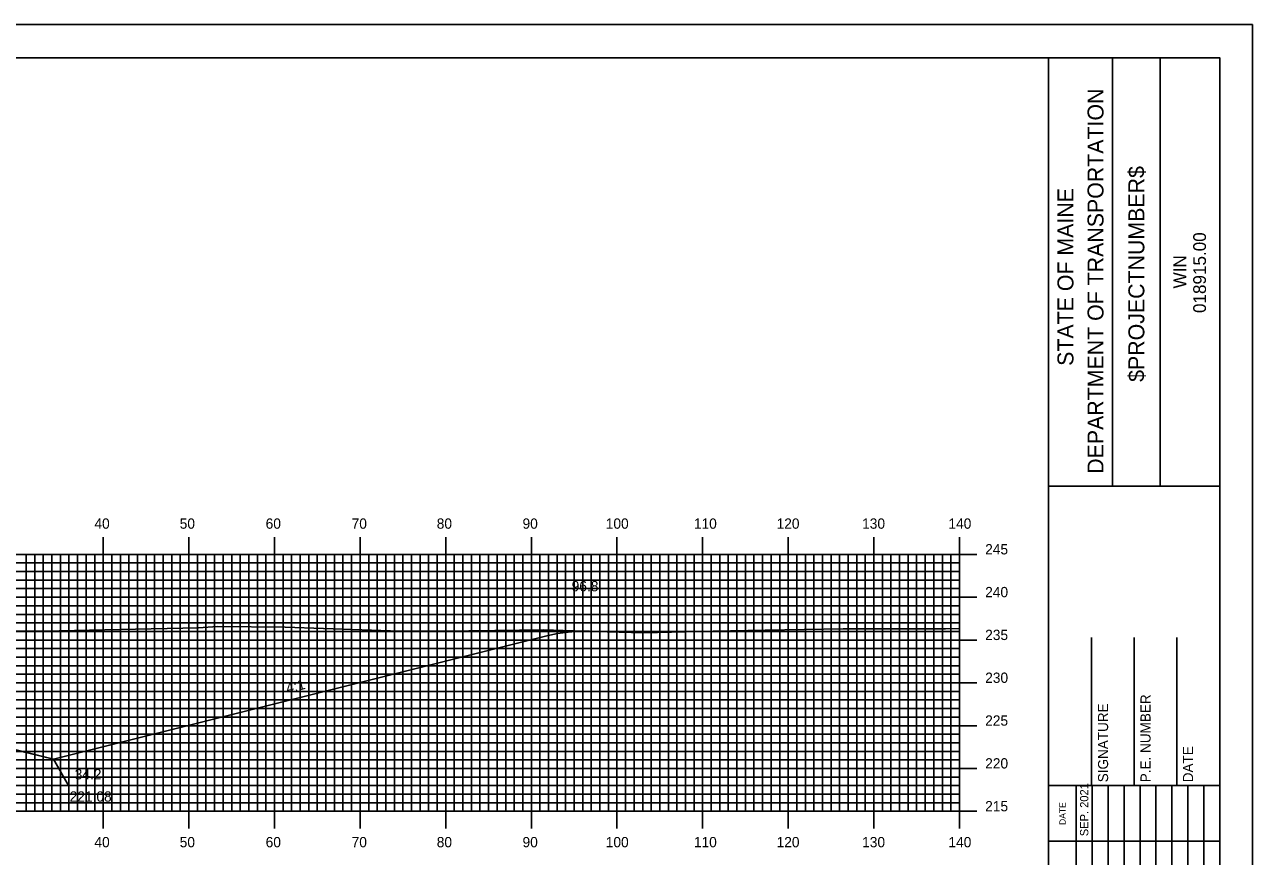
# Model space of a CAD drawing. Extents: x 1802323 to 1802666, y 442591 to 442811.
# Drawn here: x 1802519.4 to 1802662.8, y 442713.4 to 442810.5 of the extents above; entities that cross this region are included whole.
import ezdxf

# ---------------------------------------------------------------- set-up
doc = ezdxf.new("R2010")
doc.units = 0
for name, color, linetype in [('ANNOTATION', 7, 'Continuous'), ('BORDER', 7, 'Continuous'), ('D_Roadway_Centerline', 7, 'Continuous'), ('D_Roadway_SlopeLines', 7, 'Continuous'), ('D_Text_Standard', 7, 'Continuous'), ('H_V ANNOTATION', 7, 'Continuous'), ('MAJOR', 7, 'Continuous'), ('MINOR', 7, 'Continuous'), ('PLOT BOUNDARY', 7, 'Continuous'), ('S_Roadway_Centerline', 7, 'Continuous')]:
    doc.layers.add(name, color=color, linetype=linetype)

msp = doc.modelspace()

# ---------------------------------------------------------------- linework, layer by layer
at = {"layer": 'ANNOTATION'}
msp.add_lwpolyline([(1802530.23, 442721.67), (1802524.53, 442721.67), (1802522.78, 442724.74)], dxfattribs=at)
at = {"layer": 'BORDER'}
for p, q in [((1802639, 442596.67), (1802639, 442806.67)), ((1802646.46, 442756.66), (1802646.46, 442806.66)), ((1802652.05, 442756.66), (1802652.05, 442806.66)), ((1802639, 442756.65), (1802659, 442756.65)), ((1802644, 442721.67), (1802644, 442738.97)), ((1802649, 442721.67), (1802649, 442738.97)), ((1802654, 442721.67), (1802654, 442738.97)), ((1802639, 442721.67), (1802659, 442721.67))]:
    msp.add_line(p, q, dxfattribs=at)
msp.add_lwpolyline([(1802339, 442596.67), (1802659, 442596.67), (1802659, 442806.67), (1802339, 442806.67)], close=True, dxfattribs=at)
for points in [[(1802642.23, 442715.17), (1802642.23, 442721.67)], [(1802644.1, 442686.68), (1802644.1, 442721.67)], [(1802645.96, 442721.67), (1802645.96, 442686.68)], [(1802647.82, 442686.68), (1802647.82, 442721.67)], [(1802649.69, 442686.68), (1802649.69, 442721.67)], [(1802651.55, 442686.68), (1802651.55, 442721.67)], [(1802653.41, 442686.68), (1802653.41, 442721.67)], [(1802655.28, 442686.68), (1802655.28, 442721.67)], [(1802657.14, 442686.68), (1802657.14, 442721.67)], [(1802642.23, 442686.68), (1802642.23, 442720.26)], [(1802639, 442715.17), (1802659, 442715.17)]]:
    msp.add_lwpolyline(points, dxfattribs=at)
at = {"layer": 'D_Roadway_Centerline'}
msp.add_lwpolyline([(1802392.96, 442739.5), (1802394.21, 442739.46), (1802395.46, 442739.33), (1802396.71, 442739.13), (1802397.96, 442738.86), (1802454.43, 442724.74), (1802458.43, 442725.74), (1802468.6, 442728.29), (1802476.6, 442728.61), (1802488.6, 442728.85), (1802500.6, 442728.61), (1802508.6, 442728.29), (1802518.78, 442725.74), (1802522.78, 442724.74), (1802580.4, 442739.15), (1802581.65, 442739.42), (1802582.9, 442739.6), (1802584.15, 442739.69), (1802585.4, 442739.69)], dxfattribs=at)
at = {"layer": 'D_Roadway_SlopeLines'}
for points in [[(1802522.78, 442724.74), (1802580.4, 442739.15), (1802581.65, 442739.42), (1802582.9, 442739.6), (1802584.15, 442739.69), (1802585.4, 442739.69)], [(1802508.6, 442728.29), (1802522.78, 442724.74)]]:
    msp.add_lwpolyline(points, dxfattribs=at)
at = {"layer": 'MAJOR'}
for p, q in [((1802528.6, 442750.67), (1802528.6, 442748.67)), ((1802538.6, 442750.67), (1802538.6, 442748.67)), ((1802548.6, 442750.67), (1802548.6, 442748.67)), ((1802558.6, 442750.67), (1802558.6, 442748.67)), ((1802568.6, 442750.67), (1802568.6, 442748.67)), ((1802578.6, 442750.67), (1802578.6, 442748.67)), ((1802588.6, 442750.67), (1802588.6, 442748.67)), ((1802598.6, 442750.67), (1802598.6, 442748.67)), ((1802608.6, 442750.67), (1802608.6, 442748.67)), ((1802618.6, 442750.67), (1802618.6, 442748.67)), ((1802628.6, 442750.67), (1802628.6, 442748.67)), ((1802348.6, 442748.67), (1802628.6, 442748.67)), ((1802348.6, 442748.67), (1802628.6, 442748.67)), ((1802528.6, 442718.67), (1802528.6, 442748.67)), ((1802538.6, 442718.67), (1802538.6, 442748.67)), ((1802548.6, 442718.67), (1802548.6, 442748.67)), ((1802558.6, 442718.67), (1802558.6, 442748.67)), ((1802568.6, 442718.67), (1802568.6, 442748.67)), ((1802578.6, 442718.67), (1802578.6, 442748.67)), ((1802588.6, 442718.67), (1802588.6, 442748.67)), ((1802598.6, 442718.67), (1802598.6, 442748.67)), ((1802608.6, 442718.67), (1802608.6, 442748.67)), ((1802618.6, 442718.67), (1802618.6, 442748.67)), ((1802630.61, 442748.67), (1802626.6, 442748.67)), ((1802628.6, 442718.67), (1802628.6, 442748.67)), ((1802628.6, 442718.67), (1802628.6, 442748.67)), ((1802348.6, 442743.67), (1802628.6, 442743.67)), ((1802630.61, 442743.67), (1802626.6, 442743.67)), ((1802348.6, 442738.67), (1802628.6, 442738.67)), ((1802630.61, 442738.67), (1802626.6, 442738.67)), ((1802348.6, 442733.67), (1802628.6, 442733.67)), ((1802630.61, 442733.67), (1802626.6, 442733.67)), ((1802348.6, 442728.67), (1802628.6, 442728.67)), ((1802630.61, 442728.67), (1802626.6, 442728.67)), ((1802348.6, 442723.67), (1802628.6, 442723.67)), ((1802630.61, 442723.67), (1802626.6, 442723.67)), ((1802348.6, 442718.67), (1802628.6, 442718.67)), ((1802348.6, 442718.67), (1802628.6, 442718.67)), ((1802528.6, 442716.66), (1802528.6, 442718.67)), ((1802538.6, 442716.66), (1802538.6, 442718.67)), ((1802548.6, 442716.66), (1802548.6, 442718.67)), ((1802558.6, 442716.66), (1802558.6, 442718.67)), ((1802568.6, 442716.66), (1802568.6, 442718.67)), ((1802578.6, 442716.66), (1802578.6, 442718.67)), ((1802588.6, 442716.66), (1802588.6, 442718.67)), ((1802598.6, 442716.66), (1802598.6, 442718.67)), ((1802608.6, 442716.66), (1802608.6, 442718.67)), ((1802618.6, 442716.66), (1802618.6, 442718.67)), ((1802630.61, 442718.67), (1802626.6, 442718.67)), ((1802628.6, 442716.66), (1802628.6, 442718.67))]:
    msp.add_line(p, q, dxfattribs=at)
at = {"layer": 'MINOR'}
for p, q in [((1802519.6, 442718.67), (1802519.6, 442748.67)), ((1802520.6, 442718.67), (1802520.6, 442748.67)), ((1802521.6, 442718.67), (1802521.6, 442748.67)), ((1802522.6, 442718.67), (1802522.6, 442748.67)), ((1802523.6, 442718.67), (1802523.6, 442748.67)), ((1802524.6, 442718.67), (1802524.6, 442748.67)), ((1802525.6, 442718.67), (1802525.6, 442748.67)), ((1802526.6, 442718.67), (1802526.6, 442748.67)), ((1802527.6, 442718.67), (1802527.6, 442748.67)), ((1802529.6, 442718.67), (1802529.6, 442748.67)), ((1802530.6, 442718.67), (1802530.6, 442748.67)), ((1802531.6, 442718.67), (1802531.6, 442748.67)), ((1802532.6, 442718.67), (1802532.6, 442748.67)), ((1802533.6, 442718.67), (1802533.6, 442748.67)), ((1802534.6, 442718.67), (1802534.6, 442748.67)), ((1802535.6, 442718.67), (1802535.6, 442748.67)), ((1802536.6, 442718.67), (1802536.6, 442748.67)), ((1802537.6, 442718.67), (1802537.6, 442748.67)), ((1802539.6, 442718.67), (1802539.6, 442748.67)), ((1802540.6, 442718.67), (1802540.6, 442748.67)), ((1802541.6, 442718.67), (1802541.6, 442748.67)), ((1802542.6, 442718.67), (1802542.6, 442748.67)), ((1802543.6, 442718.67), (1802543.6, 442748.67)), ((1802544.6, 442718.67), (1802544.6, 442748.67)), ((1802545.6, 442718.67), (1802545.6, 442748.67)), ((1802546.6, 442718.67), (1802546.6, 442748.67)), ((1802547.6, 442718.67), (1802547.6, 442748.67)), ((1802549.6, 442718.67), (1802549.6, 442748.67)), ((1802550.6, 442718.67), (1802550.6, 442748.67)), ((1802551.6, 442718.67), (1802551.6, 442748.67)), ((1802552.6, 442718.67), (1802552.6, 442748.67)), ((1802553.6, 442718.67), (1802553.6, 442748.67)), ((1802554.6, 442718.67), (1802554.6, 442748.67)), ((1802555.6, 442718.67), (1802555.6, 442748.67)), ((1802556.6, 442718.67), (1802556.6, 442748.67)), ((1802557.6, 442718.67), (1802557.6, 442748.67)), ((1802559.6, 442718.67), (1802559.6, 442748.67)), ((1802560.6, 442718.67), (1802560.6, 442748.67)), ((1802561.6, 442718.67), (1802561.6, 442748.67)), ((1802562.6, 442718.67), (1802562.6, 442748.67)), ((1802563.6, 442718.67), (1802563.6, 442748.67)), ((1802564.6, 442718.67), (1802564.6, 442748.67)), ((1802565.6, 442718.67), (1802565.6, 442748.67)), ((1802566.6, 442718.67), (1802566.6, 442748.67)), ((1802567.6, 442718.67), (1802567.6, 442748.67)), ((1802569.6, 442718.67), (1802569.6, 442748.67)), ((1802570.6, 442718.67), (1802570.6, 442748.67)), ((1802571.6, 442718.67), (1802571.6, 442748.67)), ((1802572.6, 442718.67), (1802572.6, 442748.67)), ((1802573.6, 442718.67), (1802573.6, 442748.67)), ((1802574.6, 442718.67), (1802574.6, 442748.67)), ((1802575.6, 442718.67), (1802575.6, 442748.67)), ((1802576.6, 442718.67), (1802576.6, 442748.67)), ((1802577.6, 442718.67), (1802577.6, 442748.67)), ((1802579.6, 442718.67), (1802579.6, 442748.67)), ((1802580.6, 442718.67), (1802580.6, 442748.67)), ((1802581.6, 442718.67), (1802581.6, 442748.67)), ((1802582.6, 442718.67), (1802582.6, 442748.67)), ((1802583.6, 442718.67), (1802583.6, 442748.67)), ((1802584.6, 442718.67), (1802584.6, 442748.67)), ((1802585.6, 442718.67), (1802585.6, 442748.67)), ((1802586.6, 442718.67), (1802586.6, 442748.67)), ((1802587.6, 442718.67), (1802587.6, 442748.67)), ((1802589.6, 442718.67), (1802589.6, 442748.67)), ((1802590.6, 442718.67), (1802590.6, 442748.67)), ((1802591.6, 442718.67), (1802591.6, 442748.67)), ((1802592.6, 442718.67), (1802592.6, 442748.67)), ((1802593.6, 442718.67), (1802593.6, 442748.67)), ((1802594.6, 442718.67), (1802594.6, 442748.67)), ((1802595.6, 442718.67), (1802595.6, 442748.67)), ((1802596.6, 442718.67), (1802596.6, 442748.67)), ((1802597.6, 442718.67), (1802597.6, 442748.67)), ((1802599.6, 442718.67), (1802599.6, 442748.67)), ((1802600.6, 442718.67), (1802600.6, 442748.67)), ((1802601.6, 442718.67), (1802601.6, 442748.67)), ((1802602.6, 442718.67), (1802602.6, 442748.67)), ((1802603.6, 442718.67), (1802603.6, 442748.67)), ((1802604.6, 442718.67), (1802604.6, 442748.67)), ((1802605.6, 442718.67), (1802605.6, 442748.67)), ((1802606.6, 442718.67), (1802606.6, 442748.67)), ((1802607.6, 442718.67), (1802607.6, 442748.67)), ((1802609.6, 442718.67), (1802609.6, 442748.67)), ((1802610.6, 442718.67), (1802610.6, 442748.67)), ((1802611.6, 442718.67), (1802611.6, 442748.67)), ((1802612.6, 442718.67), (1802612.6, 442748.67)), ((1802613.6, 442718.67), (1802613.6, 442748.67)), ((1802614.6, 442718.67), (1802614.6, 442748.67)), ((1802615.6, 442718.67), (1802615.6, 442748.67)), ((1802616.6, 442718.67), (1802616.6, 442748.67)), ((1802617.6, 442718.67), (1802617.6, 442748.67)), ((1802619.6, 442718.67), (1802619.6, 442748.67)), ((1802620.6, 442718.67), (1802620.6, 442748.67)), ((1802621.6, 442718.67), (1802621.6, 442748.67)), ((1802622.6, 442718.67), (1802622.6, 442748.67)), ((1802623.6, 442718.67), (1802623.6, 442748.67)), ((1802624.6, 442718.67), (1802624.6, 442748.67)), ((1802625.6, 442718.67), (1802625.6, 442748.67)), ((1802626.6, 442718.67), (1802626.6, 442748.67)), ((1802627.6, 442718.67), (1802627.6, 442748.67)), ((1802348.6, 442747.67), (1802628.6, 442747.67)), ((1802628.6, 442747.67), (1802626.6, 442747.67)), ((1802348.6, 442746.67), (1802628.6, 442746.67)), ((1802348.6, 442745.67), (1802628.6, 442745.67)), ((1802628.6, 442746.67), (1802626.6, 442746.67)), ((1802628.6, 442745.67), (1802626.6, 442745.67)), ((1802348.6, 442744.67), (1802628.6, 442744.67)), ((1802628.6, 442744.67), (1802626.6, 442744.67)), ((1802348.6, 442742.67), (1802628.6, 442742.67)), ((1802628.6, 442742.67), (1802626.6, 442742.67)), ((1802348.6, 442741.67), (1802628.6, 442741.67)), ((1802628.6, 442741.67), (1802626.6, 442741.67)), ((1802348.6, 442740.67), (1802628.6, 442740.67)), ((1802628.6, 442740.67), (1802626.6, 442740.67)), ((1802348.6, 442739.67), (1802628.6, 442739.67)), ((1802628.6, 442739.67), (1802626.6, 442739.67)), ((1802348.6, 442737.67), (1802628.6, 442737.67)), ((1802628.6, 442737.67), (1802626.6, 442737.67)), ((1802348.6, 442736.67), (1802628.6, 442736.67)), ((1802348.6, 442735.67), (1802628.6, 442735.67)), ((1802628.6, 442736.67), (1802626.6, 442736.67)), ((1802628.6, 442735.67), (1802626.6, 442735.67)), ((1802348.6, 442734.67), (1802628.6, 442734.67)), ((1802628.6, 442734.67), (1802626.6, 442734.67)), ((1802348.6, 442732.67), (1802628.6, 442732.67)), ((1802628.6, 442732.67), (1802626.6, 442732.67)), ((1802348.6, 442731.67), (1802628.6, 442731.67)), ((1802628.6, 442731.67), (1802626.6, 442731.67)), ((1802348.6, 442730.67), (1802628.6, 442730.67)), ((1802628.6, 442730.67), (1802626.6, 442730.67)), ((1802348.6, 442729.67), (1802628.6, 442729.67)), ((1802628.6, 442729.67), (1802626.6, 442729.67)), ((1802348.6, 442727.67), (1802628.6, 442727.67)), ((1802628.6, 442727.67), (1802626.6, 442727.67)), ((1802348.6, 442726.67), (1802628.6, 442726.67)), ((1802348.6, 442725.67), (1802628.6, 442725.67)), ((1802628.6, 442726.67), (1802626.6, 442726.67)), ((1802628.6, 442725.67), (1802626.6, 442725.67)), ((1802348.6, 442724.67), (1802628.6, 442724.67)), ((1802628.6, 442724.67), (1802626.6, 442724.67)), ((1802348.6, 442722.67), (1802628.6, 442722.67)), ((1802628.6, 442722.67), (1802626.6, 442722.67)), ((1802348.6, 442721.67), (1802628.6, 442721.67)), ((1802628.6, 442721.67), (1802626.6, 442721.67)), ((1802348.6, 442720.67), (1802628.6, 442720.67)), ((1802348.6, 442719.67), (1802628.6, 442719.67)), ((1802628.6, 442720.67), (1802626.6, 442720.67)), ((1802628.6, 442719.67), (1802626.6, 442719.67))]:
    msp.add_line(p, q, dxfattribs=at)
at = {"layer": 'PLOT BOUNDARY'}
msp.add_lwpolyline([(1802322.81, 442590.55), (1802662.81, 442590.55), (1802662.81, 442810.55), (1802322.81, 442810.55)], close=True, dxfattribs=at)
at = {"layer": 'S_Roadway_Centerline'}
msp.add_lwpolyline([(1802509.99, 442739.73), (1802520.4, 442739.7), (1802521.91, 442739.69), (1802523.45, 442739.75), (1802530.53, 442739.91), (1802539.73, 442740.1), (1802541.95, 442740.25), (1802549.86, 442740.16), (1802563.29, 442739.71), (1802568.28, 442739.72), (1802574.35, 442739.79), (1802580.05, 442739.87), (1802584.63, 442739.71), (1802591.69, 442739.53), (1802599.84, 442739.72), (1802605.89, 442739.82), (1802615.01, 442739.98), (1802626.35, 442739.96), (1802626.97, 442739.97), (1802628.6, 442740.01)], dxfattribs=at)

# ---------------------------------------------------------------- texts
at = {"layer": 'ANNOTATION'}
msp.add_text('4:1', height=1.2, rotation=14.0362, dxfattribs=at).set_placement((1802550.12, 442732.44))
for s, p in [("34.2'", (1802525.27, 442722.4)), ('221.08', (1802524.68, 442719.8))]:
    msp.add_text(s, height=1.2, dxfattribs=at).set_placement(p)
at = {"layer": 'BORDER'}
for s, height, p in [('DEPARTMENT OF TRANSPORTATION', 1.8635, (1802645.42, 442758.08)), ('$PROJECTNUMBER$', 1.8635, (1802650.19, 442768.82)), ('STATE OF MAINE', 1.8635, (1802641.91, 442770.69)), ('018915.00', 1.491, (1802657.39, 442776.86)), ('WIN', 1.491, (1802655.08, 442779.73)), ('SIGNATURE', 1.181, (1802645.96, 442722.06)), ('P.E. NUMBER', 1.1811, (1802650.92, 442722.06)), ('DATE', 1.181, (1802655.88, 442722.06)), ('SEP. 2021', 0.969, (1802643.65, 442715.76)), ('DATE', 0.743, (1802641.01, 442717.08))]:
    msp.add_text(s, height=height, rotation=90, dxfattribs=at).set_placement(p)
at = {"layer": 'D_Text_Standard'}
msp.add_text("96.8'", height=1.2, dxfattribs=at).set_placement((1802583.31, 442744.36))
at = {"layer": 'H_V ANNOTATION'}
for s, p in [('40', (1802527.57, 442751.67)), ('50', (1802537.53, 442751.67)), ('60', (1802547.57, 442751.67)), ('70', (1802557.61, 442751.67)), ('80', (1802567.55, 442751.67)), ('90', (1802577.57, 442751.67)), ('100', (1802587.29, 442751.67)), ('110', (1802597.58, 442751.67)), ('120', (1802607.24, 442751.67)), ('130', (1802617.23, 442751.67)), ('140', (1802627.31, 442751.67)), ('245', (1802631.6, 442748.67)), ('240', (1802631.6, 442743.67)), ('235', (1802631.6, 442738.67)), ('230', (1802631.6, 442733.67)), ('225', (1802631.6, 442728.67)), ('220', (1802631.6, 442723.67)), ('215', (1802631.6, 442718.67)), ('40', (1802527.57, 442714.47)), ('50', (1802537.53, 442714.47)), ('60', (1802547.57, 442714.47)), ('70', (1802557.61, 442714.47)), ('80', (1802567.55, 442714.47)), ('90', (1802577.57, 442714.47)), ('100', (1802587.29, 442714.47)), ('110', (1802597.58, 442714.47)), ('120', (1802607.24, 442714.47)), ('130', (1802617.23, 442714.47)), ('140', (1802627.31, 442714.47))]:
    msp.add_text(s, height=1.2, dxfattribs=at).set_placement(p)

doc.saveas('drawing.dxf')
